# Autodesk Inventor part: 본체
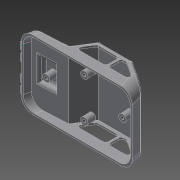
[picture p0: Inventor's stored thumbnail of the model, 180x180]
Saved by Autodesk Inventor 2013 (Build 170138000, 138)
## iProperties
Created: 2015-05
Part Number: 본체
Material: 일반
Document SubType Name: Modeling
Designer: WINDOWS7
Density: 1 g/cm^3
Author: WINDOWS7
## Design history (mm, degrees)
sketch "스케치3"
  geometry: L1 (0, 0)-(122, 0); L2 (0, 0)-(2.412, 9); L3 (2.412, 9)-(42, 11); L4 (42, 11)-(54.55, 31); L5 (54.55, 31)-(92, 31); L6 (92, 31)-(118.412, 13.392); L7 (118.412, 13.392)-(122, 0)
  constraints: 14 end point, 1 horizontal, 1 parallel
  dimensions: "d0" = 105 deg angle of L2 L1; "d1" = 105 deg angle of L7 L1; "d4" = 42 horizontal distance of L3.end L1.start; "d6" = 9 vertical distance of L1.start L2.end; "d7" = 125 deg angle of L4 L3; "d13" = 20 vertical distance of L3.end L4.end; "d17" = 31 vertical distance of L5.end L1.end; "d28" = 50 horizontal distance of L5.end L3.end; "d29" = 31.74272 distance of L5.end L6.end; "d30" = 13.3923 vertical distance of L6.end L1.end
extrude "돌출1" new body sketch "스케치3" distance "d14" = 76; taper "d15" = 0 deg
node "작업 평면1"
sketch "스케치4"
  geometry: L1 (118.412, 13.392)-(122, 0) reference; L2 (122, 0)-(0, 0) reference; L3 (0, 0)-(2.412, 9) reference; L4 (2.412, 9)-(42, 11) reference; L5 (42, 11)-(54.55, 31) reference; L6 (54.55, 31)-(92, 31) reference; L7 (92, 31)-(118.412, 13.392) reference; L8 (2.071, 0)-(3.967, 7.076); L9 (3.967, 7.076)-(43.141, 9.055); L10 (43.141, 9.055)-(55.656, 29); L11 (55.656, 29)-(91.394, 29); L12 (91.394, 29)-(116.675, 12.146); L13 (116.675, 12.146)-(119.929, 0)
  constraints: 12 end point, 6 parallel, 2 point on line
  dimensions: "d19" = 2 distance between parallel lines of L3 L8; "d20" = 2 distance between parallel lines of L4 L9; "d21" = 2 distance between parallel lines of L5 L10; "d23" = 2 distance between parallel lines of L6 L11; "d24" = 2 distance between parallel lines of L7 L12; "d25" = 2 distance between parallel lines of L1 L13
extrude "돌출2" cut sketch "스케치4" stored distance "d26" = 72; taper "d27" = 0 deg
sketch "스케치6"
  geometry: L1 (53.327, 11)-(78.903, 11); L2 (92, 31)-(54.55, 31) reference; L3 (58.974, 26)-(78.903, 26); L4 (81.903, 23)-(81.903, 14); L5 (118.412, 13.392)-(122, 0) reference; L6 (122, 0)-(0, 0) reference; L7 (0, 0)-(2.412, 9) reference; L8 (2.412, 9)-(42, 11) reference; L9 (42, 11)-(54.55, 31) reference; L10 (54.55, 31)-(92, 31) reference; L11 (92, 31)-(118.412, 13.392) reference; L12 (50.786, 15.595)-(56.433, 24.595); L13 (86.855, 11)-(103.078, 11); L14 (83.855, 14)-(83.855, 23); L15 (86.855, 26)-(89.578, 26); L16 (91.242, 25.496)-(104.742, 16.496); A1 r 3 centre (103.078, 14) between (103.078, 11) and (104.742, 16.496); A2 r 3 centre (86.855, 23) between (86.855, 26) and (83.855, 23); A3 r 3 centre (78.903, 23) between (81.903, 23) and (78.903, 26); A4 r 3 centre (78.903, 14) between (78.903, 11) and (81.903, 14); A5 r 3 centre (86.855, 14) between (83.855, 14) and (86.855, 11); A6 r 3 centre (53.327, 14) between (50.786, 15.595) and (53.327, 11); A7 r 3 centre (58.974, 23) between (58.974, 26) and (56.433, 24.595); A8 r 3 centre (89.578, 23) between (91.242, 25.496) and (89.578, 26); 2 further points
  constraints: 16 end point, 16 point on circle, 16 tangent, 8 centre point, 7 equal radius, 4 parallel, 4 point on line, 3 perpendicular, 1 horizontal
  dimensions: "d31" = 20 distance between parallel lines of L1 L2; "d32" = 15 distance between parallel lines of L1 L3; "d33" = 34 distance of point (47.903, 11) point (81.903, 11); "d35" = 5 distance between parallel lines of L9 L12; "d36" = 5 distance between parallel lines of L11 L16; "d37" = 3 radius of A1
extrude "돌출3" cut sketch "스케치6" distance "d38" = 2; taper "d39" = 0 deg
fillet "모깎기3" dims "d48" = 12
fillet "모깎기4" dims "d49" = 12
fillet "모깎기5" dims "d50" = 3
fillet "모깎기6" dims "d51" = 3
fillet "모깎기7" dims "d52" = 3
fillet "모깎기8" dims "d53" = 3
fillet "모깎기9" dims "d54" = 3
node "작업 평면2"
sketch "스케치8"
  geometry: L1 (26, 0)-(26, 55.115); L2 (64, 10.039)-(64, 16.87) reference; A1 r 4 centre (5, 0) between (9, 0) and (1, 0); A2 r 4 centre (16, 0) between (20, 0) and (12, 0); A3 r 4 centre (36, 0) between (40, 0) and (32, 0); A4 r 4 centre (47, 0) between (51, 0) and (43, 0); 3 further points
  constraints: 8 point on circle, 4 centre point, 2 end point, 1 vertical, 14 other
  dimensions: "d56" = 38 distance between parallel lines of L2 L1; "d57" = 8 diameter of A1; "d58" = 8 diameter of A2; "d59" = 8 diameter of A3; "d60" = 8 diameter of A4; "d61" = 11 distance of A2.centre A1.centre; "d62" = 11 distance of A4.centre A3.centre; "d63" = 10 distance from line of L1 A3.centre; "d64" = 10 distance from line of L1 A2.centre
extrude "돌출5" join sketch "스케치8" stored distance "d65" = 5; taper "d66" = 0 deg
chamfer "모따기1" distance "d67" = 1; stored, may be unused: second distance "d68" = 2, angle "d69" = 45 deg
chamfer "모따기2" distance "d70" = 1; stored, may be unused: second distance "d71" = 2, angle "d72" = 45 deg
chamfer "모따기3" distance "d73" = 1; stored, may be unused: second distance "d74" = 2, angle "d75" = 45 deg
chamfer "모따기4" distance "d76" = 1; stored, may be unused: second distance "d77" = 2, angle "d78" = 45 deg
sketch "스케치10"
  geometry: L1 (-31.135, 74)-(65.894, 74) reference; L2 (-30.543, 49)-(-12.543, 49); L3 (-12.543, 49)-(-12.543, 25); L4 (-12.543, 25)-(-30.543, 25); L5 (-30.543, 25)-(-30.543, 49); L6 (-30.543, 49)-(-12.543, 25); L7 (-12.543, 49)-(-30.543, 25); L8 (-43.543, 42)-(-43.543, 30) reference; 2 further points
  constraints: 12 end point, 2 midpoint, 2 parallel, 1 horizontal, 1 perpendicular
  dimensions: "d80" = 18 distance of L2.start L2.end; "d81" = 24 distance of L4.end L2.start; "d82" = 13 distance between parallel lines of L5 L8
sketch "스케치11"
  geometry: L1 (31.692, 64)-(9.457, 64) reference; L2 (5.953, 39)-(25.953, 39); L3 (25.953, 39)-(25.953, 13); L4 (25.953, 13)-(5.953, 13); L5 (5.953, 13)-(5.953, 39); L6 (5.953, 39)-(25.953, 13); L7 (25.953, 39)-(5.953, 13); L8 (-5.047, 20)-(-5.047, 32) reference; 2 further points
  constraints: 12 end point, 2 midpoint, 2 parallel, 1 horizontal, 1 perpendicular
  dimensions: "d84" = 20 distance of L2.start L2.end; "d85" = 26 distance of L4.end L2.start; "d86" = 11 distance between parallel lines of L5 L8
extrude "돌출6" join sketch "스케치11" distance "d87" = 5; taper "d88" = 0 deg
fillet "모깎기10" dims "d89" = 3
extrude "돌출7" cut sketch "스케치10" distance "d90" = 5; taper "d91" = 0 deg
fillet "모깎기11" dims "d92" = 3
fillet "모깎기12" dims "d93" = 3
fillet "모깎기13" dims "d94" = 3
sketch "스케치12"
  geometry: L1 (-29.543, 48.912)-(-27.627, 48.912) reference; L2 (-27.627, 48.912)-(-27.627, 27.916) reference; L3 (-27.627, 27.916)-(-12.63, 27.916) reference; L4 (-12.63, 46)-(-12.63, 27.916) reference; L5 (-27.627, 48.912)-(-15.543, 48.912) reference; L6 (-32.455, 26)-(-32.455, 46) reference; L7 (-15.543, 23.088)-(-29.543, 23.088) reference; L8 (-12.63, 27.916)-(-12.63, 26) reference; L9 (41.019, 72)-(39.064, 72) reference; L10 (39.064, 72)-(39.064, 74) reference; L11 (39.064, 74)-(41.019, 74) reference; L12 (41.019, 74)-(41.019, 72) reference; L13 (66.02, 1.479)-(66.02, 70.521) reference; L14 (60.987, 71.97)-(60.987, 74) reference; L15 (60.987, 74)-(62.163, 74) reference; L16 (69.376, 69.613)-(69.376, 2.387) reference; L17 (62.163, -2)-(60.987, -2) reference; L18 (60.987, -2)-(60.987, 0.03) reference; L19 (3.501, 0)-(7.479, 0) reference; L20 (7.479, 0)-(7.479, -2) reference; L21 (7.479, -2)-(4.722, -2) reference; L22 (1.059, 1)-(1.059, 71) reference; L23 (4.722, 74)-(7.479, 74) reference; L24 (7.479, 74)-(7.479, 72) reference; L25 (7.479, 72)-(3.501, 72) reference; L26 (3.501, 72)-(3.501, 0) reference; L27 (39.064, 0)-(41.019, 0) reference; L28 (41.019, 0)-(41.019, -2) reference; L29 (41.019, -2)-(39.064, -2) reference; L30 (39.064, -2)-(39.064, 0) reference; L31 (-31.135, 74)-(65.894, 74) reference; C1 r 4 at (-20.128, 36); C2 r 4 at (19.872, 14); C3 r 4 at (19.872, 58); C4 r 4 at (59.872, 36); 9 further points; 6 other entities
  constraints: 4 centre point, 12 other
  dimensions: "d95" = 8 diameter of C1; "d99" = 8 diameter of C2; "d100" = 8 diameter of C4; "d101" = 40 horizontal distance of C2.centre C4.centre; "d102" = 40 horizontal distance of C2.centre C1.centre; "d105" = 8 diameter of C3
extrude "돌출8" join sketch "스케치12" distance "d103" = 9; taper "d104" = 0 deg
sketch "스케치13"
  geometry: L1 (84.222, -38)-(-9.879, -38) reference; L2 (-22.489, -26)-(-22.489, -23.631) reference; L3 (-24.59, -22.843)-(-24.59, -19.157) reference; L4 (-22.489, -18.369)-(-22.489, -12.631) reference; L5 (-24.59, -11.843)-(-24.59, -8.157) reference; L6 (-22.489, -7.369)-(-22.489, 7.369) reference; L7 (-24.59, 8.157)-(-24.59, 11.843) reference; L8 (-22.489, 12.631)-(-22.489, 18.369) reference; L9 (-24.59, 19.157)-(-24.59, 22.843) reference; L10 (-22.489, 23.631)-(-22.489, 26) reference; L11 (-9.879, 38)-(84.222, 38) reference; L12 (96.495, 26)-(96.495, -26) reference; L13 (94.449, -24)-(94.449, 24) reference; L14 (82.176, 36)-(-7.777, 36) reference; L15 (-20.387, 24)-(-20.387, -24) reference; L16 (-7.777, -36)-(82.176, -36) reference; C1 r 4 at (0, 0) reference; C2 r 4 at (40, 22) reference; C3 r 4 at (40, -22) reference; C4 r 4 at (80, 0) reference; 29 further points; 16 other entities
  constraints: 4 coincident, 24 other
hole "구멍1" sketch "스케치13" at (0, 0), (40, 22), (80, 0), (40, -22) diameter "d106" = 3.242; stored, may be unused: countersink angle "d110" = 90 deg, drill point angle "d112" = 118 deg; dims "d107" = 9, "d108" = 4, "d109" = 2, "d111" = 11
node "작업 평면4"
  node "작업 평면3"
sketch "스케치14"
  geometry: 1 further point
node "솔리드1"
mirror "대칭1"
node "절단 모서리 투영1"
node "절단 모서리 투영2"
node "절단 모서리 투영3"
node "절단 모서리 투영4"
other parameters: "d18" = -38, "d55" = 2, "d113" = 22
